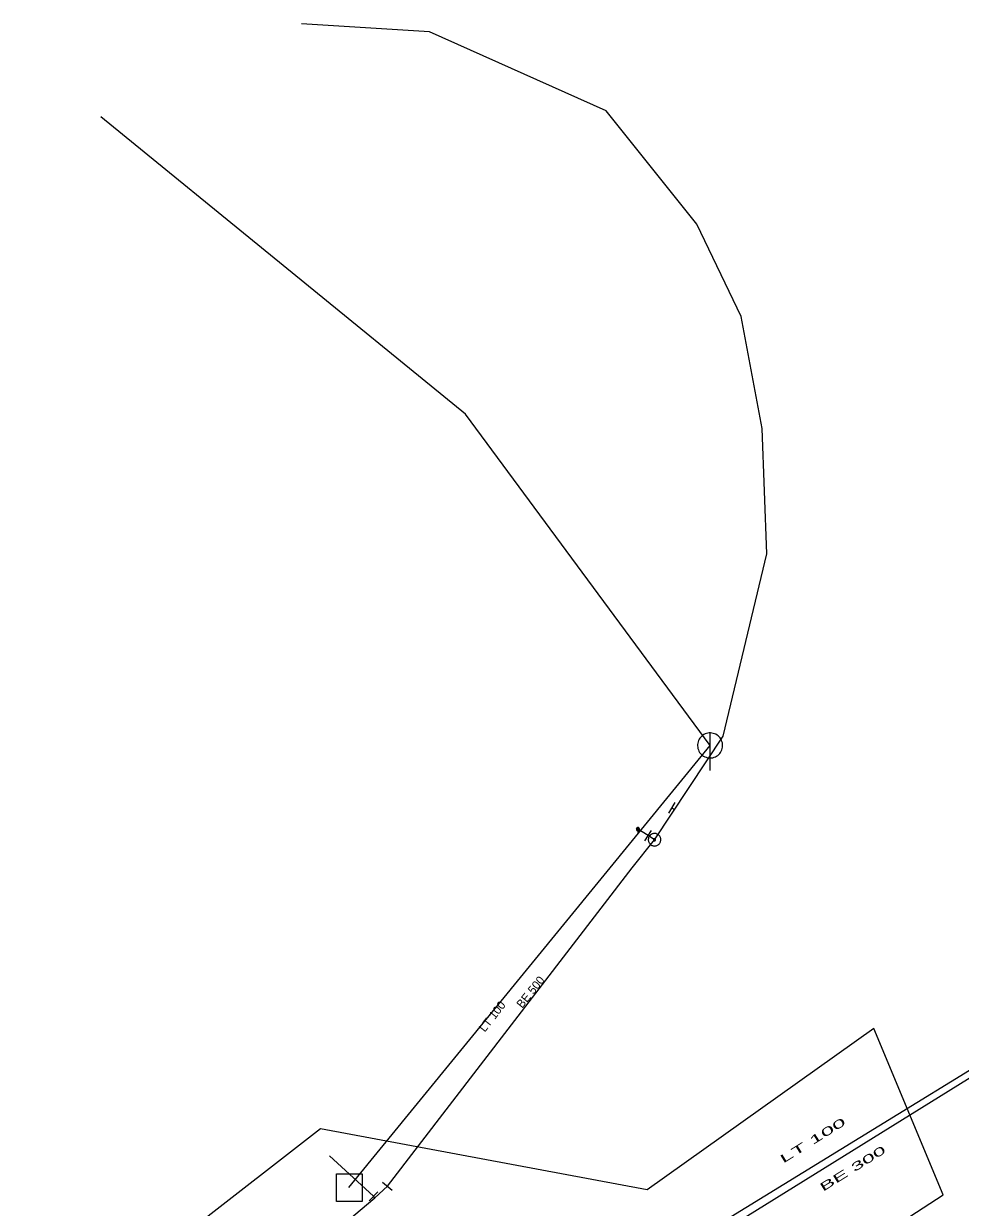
# Model space of a CAD drawing. Extents: x -688296 to -687852, y -973332 to -972816.
# Drawn here: x -688073 to -687998.3, y -973111.5 to -973017 of the extents above; entities that cross this region are included whole.
import ezdxf
from ezdxf.enums import TextEntityAlignment as Align

# ---------------------------------------------------------------- set-up
doc = ezdxf.new("R2010")
doc.units = 0
doc.header["$LTSCALE"] = 0.27
for name, color, linetype, lineweight in [('1', 7, 'Continuous', 25), ('13', 7, 'Continuous', 13), ('14', 7, 'Continuous', 13), ('17', 7, 'Continuous', 25), ('22', 7, 'Continuous', 13), ('34', 7, 'Continuous', 13), ('47', 7, 'Continuous', 13), ('9', 7, 'Continuous', 13)]:
    doc.layers.add(name, color=color, linetype=linetype, lineweight=lineweight)

msp = doc.modelspace()

# ---------------------------------------------------------------- linework, layer by layer
at = {"layer": '1'}
msp.add_lwpolyline([(-688090.469, -973137.197), (-688100.452, -973146.564), (-688079.864, -973164.439), (-688061.035, -973148.602), (-688050.242, -973162.551), (-688034.437, -973152.412), (-688045.047, -973140.009), (-687999.652, -973110.475), (-688005.19, -973097.204), (-688023.258, -973110.095), (-688049.335, -973105.21)], close=True, dxfattribs=at)
at = {"layer": '13'}
msp.add_line((-688045.106, -973110.594), (-688048.615, -973107.369), dxfattribs=at)
at = {"layer": '14', "lineweight": 25}
for p, q in [((-688047.063, -973109.905), (-688018.24, -973074.61)), ((-687989.249, -973096), (-688026.18, -973118.949))]:
    msp.add_line(p, q, dxfattribs=at)
at = {"layer": '14'}
for p, q in [((-688021.095, -973079.754), (-688021.297, -973079.592)), ((-688023.188, -973081.808), (-688024, -973081.29)), ((-688022.672, -973082.136), (-688023.188, -973081.808)), ((-688044.978, -973110.715), (-688045.106, -973110.594))]:
    msp.add_line(p, q, dxfattribs=at)
at = {"layer": '14', "lineweight": 25}
msp.add_lwpolyline([(-688018.24, -973074.61), (-688037.766, -973048.174), (-688066.854, -973024.418)], dxfattribs=at)
at = {"layer": '17'}
for points in [[(-688022.672, -973082.136), (-688017.199, -973073.873), (-688013.717, -973059.304), (-688014.099, -973049.307), (-688015.75, -973040.379), (-688019.304, -973033), (-688026.539, -973023.956), (-688040.631, -973017.647), (-688050.85, -973016.992)], [(-688063.439, -973127.129), (-688055.41, -973136.87), (-688027.175, -973118.732), (-687991.487, -973096.813), (-687978.252, -973089.283), (-687949, -973074.559)], [(-688043.984, -973109.795), (-688024.471, -973084.39), (-688022.672, -973082.136)], [(-688063.767, -973126.529), (-688044.978, -973110.715), (-688043.984, -973109.795)]]:
    msp.add_lwpolyline(points, dxfattribs=at)
at = {"layer": '22'}
msp.add_line((-688018.24, -973076.61), (-688018.239, -973073.61), dxfattribs=at)
for points in [[(-688017.24, -973074.61), (-688017.245, -973074.501), (-688017.263, -973074.393), (-688017.293, -973074.287), (-688017.333, -973074.186), (-688017.385, -973074.089), (-688017.447, -973073.999), (-688017.519, -973073.916), (-688017.599, -973073.842), (-688017.687, -973073.776), (-688017.781, -973073.721), (-688017.881, -973073.676), (-688017.986, -973073.643), (-688018.093, -973073.621), (-688018.202, -973073.611), (-688018.312, -973073.613), (-688018.42, -973073.627), (-688018.527, -973073.652), (-688018.63, -973073.689), (-688018.728, -973073.738), (-688018.82, -973073.796), (-688018.906, -973073.865), (-688018.983, -973073.942), (-688019.052, -973074.028), (-688019.111, -973074.12), (-688019.159, -973074.218), (-688019.196, -973074.321), (-688019.222, -973074.428), (-688019.236, -973074.536), (-688019.239, -973074.646), (-688019.229, -973074.755), (-688019.208, -973074.862), (-688019.174, -973074.966), (-688019.13, -973075.066), (-688019.075, -973075.161), (-688019.009, -973075.249), (-688018.935, -973075.329), (-688018.852, -973075.401), (-688018.762, -973075.463), (-688018.666, -973075.515), (-688018.564, -973075.556), (-688018.459, -973075.586), (-688018.351, -973075.604), (-688018.241, -973075.61), (-688018.132, -973075.604), (-688018.024, -973075.586), (-688017.919, -973075.557), (-688017.817, -973075.516), (-688017.72, -973075.464), (-688017.63, -973075.402), (-688017.547, -973075.331), (-688017.472, -973075.251), (-688017.407, -973075.163), (-688017.351, -973075.069), (-688017.307, -973074.969), (-688017.273, -973074.865), (-688017.251, -973074.757), (-688017.241, -973074.648)], [(-688048.043, -973108.815), (-688046.01, -973108.815), (-688046.01, -973111.008), (-688048.043, -973111.008)]]:
    msp.add_lwpolyline(points, close=True, dxfattribs=at)
at = {"layer": '34'}
for p, q in [((-688021.046, -973079.159), (-688021.547, -973080.024)), ((-688023.456, -973082.229), (-688022.918, -973081.386)), ((-688044.375, -973109.483), (-688043.593, -973110.107)), ((-688045.45, -973110.956), (-688044.761, -973110.231))]:
    msp.add_line(p, q, dxfattribs=at)
at = {"layer": '47'}
for points in [[(-688022.275, -973082.441), (-688022.246, -973082.397), (-688022.221, -973082.351), (-688022.201, -973082.303), (-688022.186, -973082.253), (-688022.176, -973082.202), (-688022.172, -973082.149), (-688022.174, -973082.097), (-688022.181, -973082.045), (-688022.192, -973081.995), (-688022.209, -973081.945), (-688022.232, -973081.897), (-688022.26, -973081.853), (-688022.291, -973081.811), (-688022.327, -973081.773), (-688022.366, -973081.739), (-688022.41, -973081.71), (-688022.456, -973081.685), (-688022.505, -973081.665), (-688022.554, -973081.65), (-688022.605, -973081.64), (-688022.658, -973081.636), (-688022.711, -973081.637), (-688022.763, -973081.644), (-688022.813, -973081.655), (-688022.862, -973081.673), (-688022.91, -973081.696), (-688022.955, -973081.723), (-688022.996, -973081.755), (-688023.034, -973081.791), (-688023.068, -973081.83), (-688023.097, -973081.874), (-688023.122, -973081.92), (-688023.143, -973081.968), (-688023.157, -973082.018), (-688023.167, -973082.069), (-688023.172, -973082.121), (-688023.171, -973082.174), (-688023.164, -973082.226), (-688023.152, -973082.277), (-688023.134, -973082.326), (-688023.111, -973082.374), (-688023.085, -973082.418), (-688023.052, -973082.46), (-688023.016, -973082.498), (-688022.977, -973082.532), (-688022.933, -973082.561), (-688022.887, -973082.586), (-688022.84, -973082.607), (-688022.789, -973082.621), (-688022.738, -973082.631), (-688022.686, -973082.636), (-688022.634, -973082.634), (-688022.582, -973082.627), (-688022.531, -973082.615), (-688022.481, -973082.598), (-688022.433, -973082.575), (-688022.39, -973082.548), (-688022.347, -973082.516), (-688022.309, -973082.48)], [(-688022.607, -973082.186), (-688022.601, -973082.178), (-688022.598, -973082.171), (-688022.594, -973082.163), (-688022.592, -973082.155), (-688022.59, -973082.146), (-688022.59, -973082.138), (-688022.59, -973082.129), (-688022.591, -973082.121), (-688022.593, -973082.112), (-688022.596, -973082.104), (-688022.6, -973082.096), (-688022.604, -973082.089), (-688022.609, -973082.082), (-688022.614, -973082.076), (-688022.621, -973082.071), (-688022.629, -973082.065), (-688022.636, -973082.062), (-688022.644, -973082.058), (-688022.652, -973082.056), (-688022.661, -973082.054), (-688022.669, -973082.054), (-688022.678, -973082.054), (-688022.686, -973082.055), (-688022.695, -973082.057), (-688022.703, -973082.06), (-688022.711, -973082.064), (-688022.718, -973082.068), (-688022.725, -973082.073), (-688022.731, -973082.078), (-688022.736, -973082.085), (-688022.742, -973082.093), (-688022.745, -973082.1), (-688022.749, -973082.108), (-688022.751, -973082.116), (-688022.753, -973082.125), (-688022.754, -973082.133), (-688022.753, -973082.142), (-688022.752, -973082.15), (-688022.75, -973082.159), (-688022.747, -973082.167), (-688022.743, -973082.175), (-688022.739, -973082.182), (-688022.734, -973082.189), (-688022.729, -973082.195), (-688022.722, -973082.2), (-688022.714, -973082.206), (-688022.707, -973082.209), (-688022.699, -973082.213), (-688022.691, -973082.215), (-688022.682, -973082.217), (-688022.674, -973082.218), (-688022.665, -973082.217), (-688022.657, -973082.216), (-688022.648, -973082.214), (-688022.64, -973082.211), (-688022.632, -973082.207), (-688022.625, -973082.203), (-688022.618, -973082.198), (-688022.612, -973082.193)]]:
    msp.add_lwpolyline(points, close=True, dxfattribs=at)
at = {"layer": '9'}
msp.add_line((-688024.001, -973081.417), (-688024.001, -973081.542), dxfattribs=at)
for points in [[(-688024.127, -973081.289), (-688024.126, -973081.302), (-688024.124, -973081.315), (-688024.121, -973081.328), (-688024.116, -973081.34), (-688024.11, -973081.352), (-688024.103, -973081.363), (-688024.095, -973081.373), (-688024.085, -973081.383), (-688024.075, -973081.391), (-688024.064, -973081.398), (-688024.052, -973081.404), (-688024.04, -973081.409), (-688024.027, -973081.412), (-688024.014, -973081.414), (-688024.001, -973081.417), (-688023.988, -973081.416), (-688023.975, -973081.414), (-688023.962, -973081.411), (-688023.95, -973081.406), (-688023.938, -973081.4), (-688023.927, -973081.393), (-688023.917, -973081.385), (-688023.907, -973081.375), (-688023.899, -973081.365), (-688023.892, -973081.354), (-688023.886, -973081.342), (-688023.881, -973081.33), (-688023.878, -973081.317), (-688023.876, -973081.304), (-688023.874, -973081.291), (-688023.875, -973081.278), (-688023.877, -973081.265), (-688023.88, -973081.252), (-688023.885, -973081.24), (-688023.891, -973081.228), (-688023.898, -973081.217), (-688023.906, -973081.207), (-688023.916, -973081.197), (-688023.926, -973081.189), (-688023.937, -973081.182), (-688023.949, -973081.176), (-688023.961, -973081.171), (-688023.974, -973081.168), (-688023.987, -973081.166), (-688024, -973081.164), (-688024.013, -973081.164), (-688024.026, -973081.166), (-688024.039, -973081.169), (-688024.051, -973081.174), (-688024.063, -973081.18), (-688024.074, -973081.187), (-688024.084, -973081.195), (-688024.094, -973081.205), (-688024.102, -973081.215), (-688024.109, -973081.226), (-688024.115, -973081.238), (-688024.12, -973081.25), (-688024.123, -973081.263), (-688024.125, -973081.276)], [(-688024.107, -973081.289), (-688024.107, -973081.3), (-688024.105, -973081.311), (-688024.102, -973081.322), (-688024.098, -973081.332), (-688024.093, -973081.342), (-688024.087, -973081.351), (-688024.08, -973081.36), (-688024.072, -973081.368), (-688024.063, -973081.375), (-688024.054, -973081.381), (-688024.044, -973081.386), (-688024.034, -973081.39), (-688024.023, -973081.393), (-688024.012, -973081.395), (-688024.001, -973081.396), (-688023.99, -973081.397), (-688023.979, -973081.395), (-688023.968, -973081.392), (-688023.958, -973081.388), (-688023.948, -973081.383), (-688023.939, -973081.377), (-688023.93, -973081.37), (-688023.922, -973081.362), (-688023.915, -973081.353), (-688023.909, -973081.344), (-688023.904, -973081.334), (-688023.9, -973081.324), (-688023.897, -973081.313), (-688023.895, -973081.302), (-688023.894, -973081.291), (-688023.894, -973081.28), (-688023.896, -973081.269), (-688023.899, -973081.258), (-688023.903, -973081.248), (-688023.908, -973081.238), (-688023.914, -973081.229), (-688023.921, -973081.22), (-688023.929, -973081.212), (-688023.938, -973081.205), (-688023.947, -973081.199), (-688023.957, -973081.194), (-688023.967, -973081.19), (-688023.978, -973081.187), (-688023.989, -973081.185), (-688024, -973081.184), (-688024.011, -973081.183), (-688024.022, -973081.185), (-688024.033, -973081.188), (-688024.043, -973081.192), (-688024.053, -973081.197), (-688024.062, -973081.203), (-688024.071, -973081.21), (-688024.079, -973081.218), (-688024.086, -973081.227), (-688024.092, -973081.236), (-688024.097, -973081.246), (-688024.101, -973081.256), (-688024.104, -973081.267), (-688024.106, -973081.278)], [(-688024.088, -973081.289), (-688024.087, -973081.298), (-688024.086, -973081.307), (-688024.083, -973081.316), (-688024.08, -973081.324), (-688024.076, -973081.332), (-688024.071, -973081.34), (-688024.065, -973081.347), (-688024.059, -973081.353), (-688024.052, -973081.359), (-688024.044, -973081.364), (-688024.036, -973081.368), (-688024.028, -973081.371), (-688024.019, -973081.374), (-688024.01, -973081.375), (-688024.001, -973081.378), (-688023.992, -973081.377), (-688023.983, -973081.376), (-688023.974, -973081.373), (-688023.966, -973081.37), (-688023.958, -973081.366), (-688023.95, -973081.361), (-688023.943, -973081.355), (-688023.937, -973081.349), (-688023.931, -973081.342), (-688023.926, -973081.334), (-688023.922, -973081.326), (-688023.919, -973081.318), (-688023.916, -973081.309), (-688023.915, -973081.3), (-688023.913, -973081.291), (-688023.914, -973081.282), (-688023.915, -973081.273), (-688023.918, -973081.264), (-688023.921, -973081.256), (-688023.925, -973081.248), (-688023.93, -973081.24), (-688023.936, -973081.233), (-688023.942, -973081.227), (-688023.949, -973081.221), (-688023.957, -973081.216), (-688023.965, -973081.212), (-688023.973, -973081.209), (-688023.982, -973081.206), (-688023.991, -973081.205), (-688024, -973081.203), (-688024.009, -973081.203), (-688024.018, -973081.204), (-688024.027, -973081.207), (-688024.035, -973081.21), (-688024.043, -973081.214), (-688024.051, -973081.219), (-688024.058, -973081.225), (-688024.064, -973081.231), (-688024.07, -973081.238), (-688024.075, -973081.246), (-688024.079, -973081.254), (-688024.082, -973081.262), (-688024.085, -973081.271), (-688024.086, -973081.28)], [(-688024.068, -973081.289), (-688024.068, -973081.296), (-688024.066, -973081.303), (-688024.065, -973081.31), (-688024.062, -973081.316), (-688024.059, -973081.322), (-688024.055, -973081.328), (-688024.051, -973081.334), (-688024.046, -973081.339), (-688024.04, -973081.343), (-688024.034, -973081.347), (-688024.028, -973081.35), (-688024.022, -973081.353), (-688024.015, -973081.354), (-688024.008, -973081.356), (-688024.001, -973081.357), (-688023.994, -973081.358), (-688023.987, -973081.356), (-688023.98, -973081.355), (-688023.974, -973081.352), (-688023.967, -973081.349), (-688023.962, -973081.345), (-688023.956, -973081.341), (-688023.951, -973081.336), (-688023.947, -973081.33), (-688023.943, -973081.324), (-688023.94, -973081.318), (-688023.937, -973081.312), (-688023.935, -973081.305), (-688023.934, -973081.298), (-688023.933, -973081.291), (-688023.933, -973081.284), (-688023.934, -973081.277), (-688023.936, -973081.27), (-688023.939, -973081.264), (-688023.942, -973081.257), (-688023.946, -973081.252), (-688023.95, -973081.246), (-688023.955, -973081.241), (-688023.961, -973081.237), (-688023.966, -973081.233), (-688023.973, -973081.23), (-688023.979, -973081.227), (-688023.986, -973081.225), (-688023.993, -973081.224), (-688024, -973081.223), (-688024.007, -973081.222), (-688024.014, -973081.223), (-688024.021, -973081.225), (-688024.027, -973081.228), (-688024.033, -973081.231), (-688024.039, -973081.235), (-688024.045, -973081.239), (-688024.05, -973081.244), (-688024.054, -973081.25), (-688024.058, -973081.255), (-688024.061, -973081.262), (-688024.064, -973081.268), (-688024.065, -973081.275), (-688024.067, -973081.282)], [(-688024.048, -973081.289), (-688024.048, -973081.294), (-688024.047, -973081.299), (-688024.046, -973081.304), (-688024.044, -973081.308), (-688024.042, -973081.313), (-688024.039, -973081.317), (-688024.036, -973081.32), (-688024.032, -973081.324), (-688024.029, -973081.327), (-688024.025, -973081.33), (-688024.02, -973081.332), (-688024.016, -973081.334), (-688024.011, -973081.335), (-688024.006, -973081.336), (-688024.001, -973081.337), (-688023.996, -973081.338), (-688023.991, -973081.337), (-688023.986, -973081.336), (-688023.982, -973081.334), (-688023.977, -973081.332), (-688023.973, -973081.329), (-688023.969, -973081.326), (-688023.966, -973081.322), (-688023.963, -973081.319), (-688023.96, -973081.315), (-688023.958, -973081.31), (-688023.956, -973081.306), (-688023.955, -973081.301), (-688023.954, -973081.296), (-688023.954, -973081.291), (-688023.953, -973081.286), (-688023.954, -973081.281), (-688023.955, -973081.276), (-688023.957, -973081.272), (-688023.959, -973081.267), (-688023.962, -973081.263), (-688023.965, -973081.259), (-688023.968, -973081.256), (-688023.972, -973081.253), (-688023.976, -973081.25), (-688023.981, -973081.248), (-688023.985, -973081.246), (-688023.99, -973081.245), (-688023.995, -973081.244), (-688024, -973081.243), (-688024.005, -973081.242), (-688024.01, -973081.243), (-688024.015, -973081.244), (-688024.019, -973081.246), (-688024.024, -973081.248), (-688024.028, -973081.251), (-688024.031, -973081.254), (-688024.035, -973081.257), (-688024.038, -973081.261), (-688024.041, -973081.265), (-688024.043, -973081.27), (-688024.045, -973081.274), (-688024.046, -973081.279), (-688024.047, -973081.284)], [(-688024.028, -973081.289), (-688024.028, -973081.292), (-688024.028, -973081.295), (-688024.027, -973081.297), (-688024.026, -973081.3), (-688024.025, -973081.303), (-688024.023, -973081.305), (-688024.021, -973081.307), (-688024.019, -973081.309), (-688024.017, -973081.311), (-688024.015, -973081.313), (-688024.012, -973081.314), (-688024.009, -973081.315), (-688024.007, -973081.316), (-688024.004, -973081.316), (-688024.001, -973081.316), (-688023.998, -973081.318), (-688023.995, -973081.318), (-688023.992, -973081.317), (-688023.99, -973081.316), (-688023.987, -973081.315), (-688023.985, -973081.313), (-688023.982, -973081.311), (-688023.98, -973081.309), (-688023.979, -973081.307), (-688023.977, -973081.305), (-688023.976, -973081.302), (-688023.975, -973081.299), (-688023.974, -973081.297), (-688023.974, -973081.294), (-688023.972, -973081.291), (-688023.973, -973081.288), (-688023.973, -973081.285), (-688023.974, -973081.282), (-688023.975, -973081.28), (-688023.976, -973081.277), (-688023.978, -973081.275), (-688023.979, -973081.272), (-688023.981, -973081.27), (-688023.984, -973081.269), (-688023.986, -973081.267), (-688023.989, -973081.266), (-688023.991, -973081.265), (-688023.994, -973081.264), (-688023.997, -973081.264), (-688024, -973081.262), (-688024.003, -973081.262), (-688024.006, -973081.262), (-688024.008, -973081.263), (-688024.011, -973081.264), (-688024.014, -973081.265), (-688024.016, -973081.267), (-688024.018, -973081.268), (-688024.02, -973081.27), (-688024.022, -973081.273), (-688024.024, -973081.275), (-688024.025, -973081.278), (-688024.026, -973081.28), (-688024.027, -973081.283), (-688024.027, -973081.286)], [(-688024.009, -973081.289), (-688024.009, -973081.29), (-688024.009, -973081.291), (-688024.008, -973081.291), (-688024.008, -973081.292), (-688024.008, -973081.293), (-688024.007, -973081.294), (-688024.007, -973081.294), (-688024.006, -973081.295), (-688024.006, -973081.295), (-688024.005, -973081.296), (-688024.004, -973081.296), (-688024.003, -973081.296), (-688024.003, -973081.297), (-688024.002, -973081.298), (-688024.001, -973081.298), (-688024, -973081.298), (-688023.999, -973081.298), (-688023.999, -973081.298), (-688023.998, -973081.298), (-688023.997, -973081.298), (-688023.996, -973081.297), (-688023.996, -973081.297), (-688023.995, -973081.296), (-688023.995, -973081.296), (-688023.994, -973081.295), (-688023.994, -973081.294), (-688023.993, -973081.293), (-688023.993, -973081.293), (-688023.993, -973081.292), (-688023.992, -973081.291), (-688023.992, -973081.29), (-688023.992, -973081.289), (-688023.992, -973081.289), (-688023.993, -973081.288), (-688023.993, -973081.287), (-688023.994, -973081.286), (-688023.994, -973081.286), (-688023.995, -973081.285), (-688023.995, -973081.285), (-688023.996, -973081.284), (-688023.997, -973081.284), (-688023.998, -973081.283), (-688023.998, -973081.283), (-688023.999, -973081.283), (-688024, -973081.282), (-688024.001, -973081.282), (-688024.002, -973081.281), (-688024.002, -973081.281), (-688024.003, -973081.282), (-688024.004, -973081.282), (-688024.005, -973081.283), (-688024.005, -973081.283), (-688024.006, -973081.284), (-688024.006, -973081.284), (-688024.007, -973081.285), (-688024.007, -973081.286), (-688024.007, -973081.287), (-688024.008, -973081.287), (-688024.008, -973081.288)]]:
    msp.add_lwpolyline(points, close=True, dxfattribs=at)
msp.add_lwpolyline([(-688023.97, -973081.508), (-688024.001, -973081.542), (-688024.032, -973081.506)], dxfattribs=at)

# ---------------------------------------------------------------- texts
at = {"layer": '1'}
for s, rotation, p in [('BE 500', 51, (-688032.3137, -973094.5002)), ('BE 500', 51, (-688032.3137, -973094.5002)), ('BE 500', 51, (-688032.3137, -973094.5002)), ('BE 500', 51, (-688032.3137, -973094.5002)), ('BE 500', 51, (-688032.3137, -973094.5002)), ('LT 100', 52, (-688035.3604, -973096.4457)), ('LT 100', 52, (-688035.3604, -973096.4457)), ('LT 100', 52, (-688035.3604, -973096.4457)), ('LT 100', 52, (-688035.3604, -973096.4457)), ('LT 100', 52, (-688035.3604, -973096.4457))]:
    msp.add_text(s, height=0.6667, rotation=rotation, dxfattribs=at).set_placement(p, align=Align.CENTER)
for s, width, p in [('LT 100', 2.15, (-688009.8786, -973106.411)), ('LT 100', 2.15, (-688009.8786, -973106.411)), ('LT 100', 2.15, (-688009.8786, -973106.411)), ('LT 100', 2.15, (-688009.8786, -973106.411)), ('LT 100', 2.15, (-688009.8786, -973106.411)), ('BE 300', 2.05, (-688006.6926, -973108.656)), ('BE 300', 2.05, (-688006.6926, -973108.656)), ('BE 300', 2.05, (-688006.6926, -973108.656)), ('BE 300', 2.05, (-688006.6926, -973108.656)), ('BE 300', 2.05, (-688006.6926, -973108.656))]:
    msp.add_text(s, height=0.6667, rotation=32, dxfattribs=dict(at, width=width)).set_placement(p, align=Align.CENTER)

doc.saveas('drawing.dxf')
